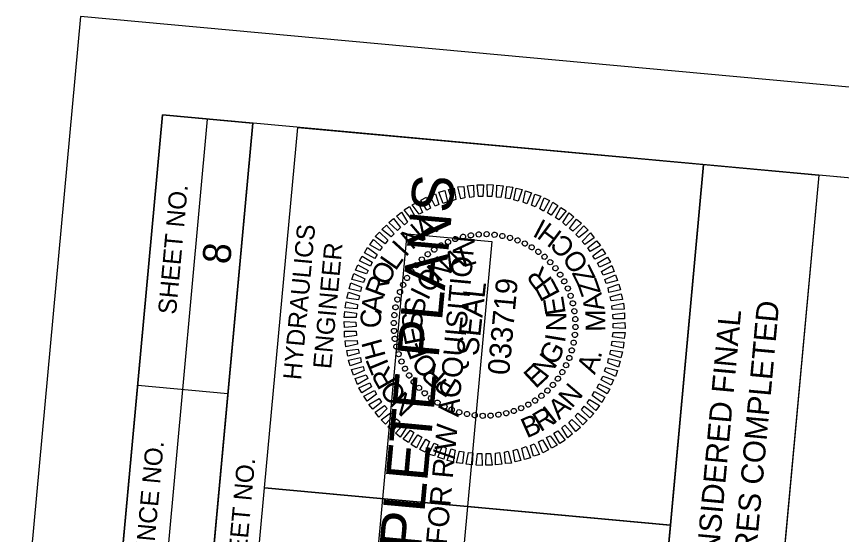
# Model space of a CAD drawing. Extents: x 2012234 to 2013485, y 445879 to 447846.
# Drawn here: x 2012372.3 to 2012600.1, y 447702.9 to 447846 of the extents above; entities that cross this region are included whole.
import ezdxf

# ---------------------------------------------------------------- set-up
doc = ezdxf.new("R2010")
doc.units = 0
for name, color, linetype in [('Sheet Clip Boundary CELL', 7, 'Continuous'), ('Sheet Data Field CELL', 7, 'Continuous'), ('Sheet Plan And Profile CELL', 7, 'Continuous'), ('Sheet Plot Border Outside CELL', 7, 'Continuous'), ('Sheet Professional Seal CELL', 7, 'Continuous'), ('Sheet Profile Grid Minor CELL', 7, 'Continuous'), ('Sheet Sticker Exception Certification CELL', 7, 'Continuous'), ('Sheet Sticker Incomplete CELL', 7, 'Continuous')]:
    doc.layers.add(name, color=color, linetype=linetype)

msp = doc.modelspace()

# ---------------------------------------------------------------- linework, layer by layer
at = {"layer": 'Sheet Clip Boundary CELL'}
msp.add_lwpolyline([(2012286.31, 446445.78), (2012511.43, 446429.21), (2012750.66, 446410.08), (2013333.05, 446362.08), (2013458.14, 447722.64), (2012593.82, 447802.11), (2012575.5, 447602.9), (2012460.65, 447613.46), (2012442.34, 447414.28), (2012375.93, 447420.39)], close=True, dxfattribs=at)
at = {"layer": 'Sheet Plan And Profile CELL'}
for p, q in [((2012406.74, 447618.42), (2012425.05, 447817.63)), ((2012419.18, 447617.27), (2012437.5, 447816.48)), ((2012405.74, 447744.09), (2012430.63, 447741.8)), ((2012440.79, 447715.76), (2012552.77, 447705.46))]:
    msp.add_line(p, q, dxfattribs=at)
for points in [[(2012412.56, 447818.78), (2012275.22, 446325.08), (2013320.81, 446228.94), (2013458.14, 447722.64)], [(2012394.24, 447619.57), (2012412.56, 447818.78), (2012437.5, 447816.48), (2012419.18, 447617.27)], [(2012440.79, 447715.76), (2012449.95, 447815.34), (2012561.97, 447805.04), (2012552.82, 447705.46)], [(2012431.63, 447616.13), (2012440.79, 447715.76), (2012552.82, 447705.46), (2012543.66, 447605.83)]]:
    msp.add_lwpolyline(points, close=True, dxfattribs=at)
at = {"layer": 'Sheet Plot Border Outside CELL'}
msp.add_lwpolyline([(2013329.68, 446052.39), (2013485.33, 447745.24), (2012389.95, 447845.96), (2012234.3, 446153.1)], close=True, dxfattribs=at)
at = {"layer": 'Sheet Professional Seal CELL'}
for p, q in [((2012497.69, 447785.54), (2012497.69, 447785.54)), ((2012499.92, 447785.74), (2012499.92, 447785.74)), ((2012502.08, 447785.84), (2012502.08, 447785.84)), ((2012504.28, 447785.69), (2012504.28, 447785.69)), ((2012506.46, 447785.34), (2012506.46, 447785.34)), ((2012491.44, 447783.71), (2012491.44, 447783.71)), ((2012493.48, 447784.52), (2012493.48, 447784.52)), ((2012495.54, 447785.14), (2012495.54, 447785.14)), ((2012508.56, 447784.79), (2012508.56, 447784.79)), ((2012510.61, 447784.15), (2012510.61, 447784.15)), ((2012512.64, 447783.26), (2012512.64, 447783.26)), ((2012487.59, 447781.65), (2012487.59, 447781.65)), ((2012489.45, 447782.73), (2012489.45, 447782.73)), ((2012514.55, 447782.18), (2012514.55, 447782.18)), ((2012516.4, 447781.01), (2012516.4, 447781.01)), ((2012484.17, 447778.9), (2012484.17, 447778.9)), ((2012485.81, 447780.31), (2012485.81, 447780.31)), ((2012518.08, 447779.6), (2012518.08, 447779.6)), ((2012482.67, 447777.28), (2012482.67, 447777.28)), ((2012519.7, 447778.1), (2012519.7, 447778.1)), ((2012521.1, 447776.46), (2012521.1, 447776.46)), ((2012481.26, 447775.6), (2012481.26, 447775.6)), ((2012522.45, 447774.68), (2012522.45, 447774.68)), ((2012479.01, 447771.85), (2012479.01, 447771.85)), ((2012480.08, 447773.75), (2012480.08, 447773.75)), ((2012523.53, 447772.82), (2012523.53, 447772.82)), ((2012478.12, 447769.82), (2012478.12, 447769.82)), ((2012524.5, 447770.83), (2012524.5, 447770.83)), ((2012477.48, 447767.77), (2012477.48, 447767.77)), ((2012525.32, 447768.79), (2012525.32, 447768.79)), ((2012476.93, 447765.66), (2012476.93, 447765.66)), ((2012525.93, 447766.73), (2012525.93, 447766.73)), ((2012476.58, 447763.48), (2012476.58, 447763.48)), ((2012526.34, 447764.58), (2012526.34, 447764.58)), ((2012476.43, 447761.29), (2012476.43, 447761.29)), ((2012501.53, 447760.74), (2012501.53, 447760.74)), ((2012526.54, 447762.35), (2012526.54, 447762.35)), ((2012476.53, 447759.12), (2012476.53, 447759.12)), ((2012526.64, 447760.19), (2012526.64, 447760.19)), ((2012476.73, 447756.89), (2012476.73, 447756.89)), ((2012526.14, 447755.81), (2012526.14, 447755.81)), ((2012526.49, 447757.99), (2012526.49, 447757.99)), ((2012477.13, 447754.74), (2012477.13, 447754.74)), ((2012525.59, 447753.7), (2012525.59, 447753.7)), ((2012477.75, 447752.68), (2012477.75, 447752.68)), ((2012524.95, 447751.65), (2012524.95, 447751.65)), ((2012478.56, 447750.65), (2012478.56, 447750.65)), ((2012524.06, 447749.63), (2012524.06, 447749.63)), ((2012479.53, 447748.65), (2012479.53, 447748.65)), ((2012480.62, 447746.79), (2012480.62, 447746.79)), ((2012522.98, 447747.72), (2012522.98, 447747.72)), ((2012481.96, 447745.01), (2012481.96, 447745.01)), ((2012521.81, 447745.87), (2012521.81, 447745.87)), ((2012483.37, 447743.38), (2012483.37, 447743.38)), ((2012518.89, 447742.57), (2012518.89, 447742.57)), ((2012520.4, 447744.19), (2012520.4, 447744.19)), ((2012484.99, 447741.87), (2012484.99, 447741.87)), ((2012486.66, 447740.46), (2012486.66, 447740.46)), ((2012515.48, 447739.82), (2012515.48, 447739.82)), ((2012517.26, 447741.16), (2012517.26, 447741.16)), ((2012488.51, 447739.29), (2012488.51, 447739.29)), ((2012490.42, 447738.21), (2012490.42, 447738.21)), ((2012511.62, 447737.77), (2012511.62, 447737.77)), ((2012513.62, 447738.74), (2012513.62, 447738.74)), ((2012492.45, 447737.32), (2012492.45, 447737.32)), ((2012494.5, 447736.68), (2012494.5, 447736.68)), ((2012496.61, 447736.13), (2012496.61, 447736.13)), ((2012498.79, 447735.78), (2012498.79, 447735.78)), ((2012500.98, 447735.63), (2012500.98, 447735.63)), ((2012503.15, 447735.73), (2012503.15, 447735.73)), ((2012505.38, 447735.93), (2012505.38, 447735.93)), ((2012507.52, 447736.33), (2012507.52, 447736.33)), ((2012509.59, 447736.95), (2012509.59, 447736.95))]:
    msp.add_line(p, q, dxfattribs=at)
for points in [[(2012495, 447795.58), (2012494.14, 447798.87), (2012495.81, 447799.02), (2012496.07, 447795.83)], [(2012497.44, 447795.96), (2012496.78, 447799.18), (2012498.5, 447799.33), (2012498.51, 447796.16)], [(2012499.87, 447796.19), (2012499.47, 447799.49), (2012501.18, 447799.48), (2012501.08, 447796.28)], [(2012502.29, 447796.27), (2012502.19, 447799.54), (2012503.89, 447799.48), (2012503.49, 447796.26)], [(2012504.78, 447796.09), (2012504.93, 447799.34), (2012506.62, 447799.18), (2012505.98, 447795.98)], [(2012507.27, 447795.81), (2012507.67, 447799.04), (2012509.3, 447798.78), (2012508.45, 447795.6)], [(2012487.88, 447793.52), (2012486.39, 447796.47), (2012487.99, 447796.98), (2012488.88, 447794.03)], [(2012490.11, 447794.32), (2012488.89, 447797.4), (2012490.54, 447797.9), (2012491.25, 447794.72)], [(2012492.53, 447795), (2012491.52, 447798.16), (2012493.11, 447798.57), (2012493.62, 447795.41)], [(2012509.63, 447795.34), (2012510.23, 447798.5), (2012511.9, 447798.14), (2012510.81, 447794.98)], [(2012512.14, 447794.71), (2012512.82, 447797.76), (2012514.48, 447797.25), (2012513.15, 447794.21)], [(2012514.47, 447793.84), (2012515.4, 447796.87), (2012517.01, 447796.37), (2012515.48, 447793.35)], [(2012483.41, 447791.32), (2012481.54, 447793.96), (2012483.07, 447794.77), (2012484.41, 447791.83)], [(2012485.57, 447792.43), (2012483.92, 447795.24), (2012485.5, 447796.05), (2012486.63, 447793.04)], [(2012516.79, 447792.87), (2012517.97, 447795.88), (2012519.45, 447795.09), (2012517.78, 447792.23)], [(2012518.89, 447791.68), (2012520.32, 447794.66), (2012521.79, 447793.77), (2012519.94, 447791.08)], [(2012481.33, 447790.01), (2012479.3, 447792.51), (2012480.74, 447793.43), (2012482.39, 447790.61)], [(2012521.09, 447790.47), (2012522.59, 447793.19), (2012524.07, 447792.31), (2012521.98, 447789.79)], [(2012477.47, 447786.8), (2012475.07, 447789.08), (2012476.37, 447790.16), (2012478.3, 447787.68)], [(2012479.38, 447788.43), (2012477.23, 447790.79), (2012478.54, 447791.87), (2012480.24, 447789.1)], [(2012523.12, 447789.08), (2012524.87, 447791.73), (2012526.17, 447790.61), (2012523.94, 447788.2)], [(2012524.97, 447787.4), (2012526.91, 447789.93), (2012528.27, 447788.86), (2012525.86, 447786.67)], [(2012475.75, 447785.05), (2012473.18, 447787.14), (2012474.4, 447788.34), (2012476.53, 447785.93)], [(2012526.73, 447785.73), (2012528.91, 447788.14), (2012530.1, 447786.93), (2012527.56, 447784.95)], [(2012474.07, 447783.14), (2012471.34, 447785.15), (2012472.51, 447786.35), (2012474.77, 447784.19)], [(2012528.46, 447783.82), (2012530.73, 447786.17), (2012531.76, 447784.82), (2012529.18, 447782.95)], [(2012472.55, 447781.33), (2012469.83, 447782.93), (2012470.82, 447784.35), (2012473.23, 447782.22)], [(2012530.05, 447782.01), (2012532.44, 447784), (2012533.53, 447782.7), (2012530.66, 447781)], [(2012471.19, 447779.14), (2012468.37, 447780.66), (2012469.21, 447782.14), (2012471.84, 447780.19)], [(2012531.41, 447779.88), (2012534, 447781.8), (2012534.92, 447780.36), (2012531.97, 447778.88)], [(2012470.04, 447776.99), (2012467.01, 447778.42), (2012467.73, 447779.76), (2012470.49, 447778.1)], [(2012532.73, 447777.85), (2012535.44, 447779.46), (2012536.27, 447778.08), (2012533.23, 447776.7)], [(2012468.94, 447774.83), (2012465.92, 447775.86), (2012466.56, 447777.36), (2012469.38, 447775.84)], [(2012533.77, 447775.55), (2012536.63, 447777.14), (2012537.29, 447775.52), (2012534.28, 447774.55)], [(2012468.07, 447772.5), (2012464.88, 447773.29), (2012465.43, 447774.95), (2012468.41, 447773.52)], [(2012534.77, 447773.3), (2012537.71, 447774.63), (2012538.26, 447773.02), (2012535.12, 447772.16)], [(2012467.29, 447770.01), (2012464.14, 447770.75), (2012464.54, 447772.37), (2012467.55, 447771.19)], [(2012535.62, 447771.01), (2012538.62, 447772.04), (2012539.08, 447770.49), (2012535.8, 447769.74)], [(2012466.67, 447767.66), (2012463.45, 447768.15), (2012463.9, 447769.77), (2012466.98, 447768.83)], [(2012466.29, 447765.18), (2012463.06, 447765.48), (2012463.26, 447767.12), (2012466.45, 447766.37)], [(2012536.19, 447768.5), (2012539.28, 447769.37), (2012539.59, 447767.78), (2012536.44, 447767.42)], [(2012536.62, 447766.05), (2012539.85, 447766.8), (2012540.04, 447765.08), (2012536.77, 447764.98)], [(2012466.02, 447762.8), (2012462.76, 447762.84), (2012462.96, 447764.48), (2012466.18, 447763.99)], [(2012536.94, 447763.61), (2012540.2, 447764.11), (2012540.2, 447762.45), (2012536.98, 447762.4)], [(2012466.04, 447760.28), (2012462.81, 447760.03), (2012462.76, 447761.74), (2012466, 447761.49)], [(2012537.02, 447761.19), (2012540.26, 447761.44), (2012540.3, 447759.73), (2012537.06, 447759.98)], [(2012466.12, 447757.87), (2012462.86, 447757.36), (2012462.86, 447759.02), (2012466.08, 447759.07)], [(2012537.04, 447758.68), (2012540.3, 447758.63), (2012540.1, 447756.99), (2012536.88, 447757.49)], [(2012466.45, 447755.43), (2012463.22, 447754.67), (2012463.02, 447756.39), (2012466.3, 447756.49)], [(2012536.77, 447756.29), (2012540.01, 447755.99), (2012539.81, 447754.35), (2012536.61, 447755.1)], [(2012466.88, 447752.98), (2012463.78, 447752.11), (2012463.48, 447753.69), (2012466.62, 447754.05)], [(2012536.4, 447753.81), (2012539.61, 447753.32), (2012539.16, 447751.7), (2012536.09, 447752.64)], [(2012467.45, 447750.46), (2012464.44, 447749.43), (2012463.98, 447750.98), (2012467.26, 447751.74)], [(2012535.78, 447751.46), (2012538.92, 447750.72), (2012538.52, 447749.1), (2012535.52, 447750.28)], [(2012468.29, 447748.18), (2012465.36, 447746.84), (2012464.8, 447748.45), (2012467.95, 447749.31)], [(2012535, 447748.97), (2012538.19, 447748.18), (2012537.63, 447746.52), (2012534.65, 447747.95)], [(2012469.29, 447745.93), (2012466.43, 447744.33), (2012465.78, 447745.95), (2012468.78, 447746.93)], [(2012534.13, 447746.64), (2012537.15, 447745.61), (2012536.51, 447744.11), (2012533.68, 447745.63)], [(2012470.33, 447743.62), (2012467.63, 447742.01), (2012466.8, 447743.39), (2012469.84, 447744.77)], [(2012533.03, 447744.48), (2012536.06, 447743.05), (2012535.33, 447741.71), (2012532.57, 447743.37)], [(2012471.65, 447741.59), (2012469.07, 447739.67), (2012468.15, 447741.11), (2012471.09, 447742.6)], [(2012531.87, 447742.33), (2012534.7, 447740.82), (2012533.86, 447739.34), (2012531.23, 447741.29)], [(2012473.01, 447739.46), (2012470.62, 447737.47), (2012469.54, 447738.77), (2012472.4, 447740.47)], [(2012530.52, 447740.15), (2012533.23, 447738.54), (2012532.25, 447737.12), (2012529.83, 447739.25)], [(2012474.61, 447737.65), (2012472.33, 447735.3), (2012471.3, 447736.65), (2012473.88, 447738.52)], [(2012529, 447738.33), (2012531.72, 447736.32), (2012530.56, 447735.12), (2012528.3, 447737.29)], [(2012476.34, 447735.74), (2012474.16, 447733.33), (2012472.96, 447734.54), (2012475.51, 447736.52)], [(2012527.31, 447736.42), (2012529.88, 447734.33), (2012528.67, 447733.14), (2012526.53, 447735.54)], [(2012478.09, 447734.07), (2012476.15, 447731.54), (2012474.8, 447732.62), (2012477.21, 447734.8)], [(2012479.95, 447732.39), (2012478.2, 447729.74), (2012476.89, 447730.87), (2012479.12, 447733.27)], [(2012523.69, 447733.04), (2012525.83, 447730.68), (2012524.53, 447729.6), (2012522.82, 447732.37)], [(2012525.6, 447734.67), (2012528, 447732.39), (2012526.69, 447731.31), (2012524.76, 447733.8)], [(2012481.98, 447731), (2012480.47, 447728.28), (2012479, 447729.17), (2012481.09, 447731.69)], [(2012521.74, 447731.46), (2012523.77, 447728.97), (2012522.33, 447728.04), (2012520.68, 447730.86)], [(2012484.18, 447729.8), (2012482.75, 447726.81), (2012481.27, 447727.7), (2012483.13, 447730.39)], [(2012486.28, 447728.6), (2012485.1, 447725.59), (2012483.61, 447726.38), (2012485.28, 447729.24)], [(2012517.5, 447729.04), (2012519.15, 447726.23), (2012517.57, 447725.42), (2012516.44, 447728.44)], [(2012519.66, 447730.15), (2012521.52, 447727.52), (2012519.99, 447726.7), (2012518.66, 447729.64)], [(2012488.6, 447727.63), (2012487.67, 447724.6), (2012486.06, 447725.1), (2012487.59, 447728.13)], [(2012490.93, 447726.76), (2012490.25, 447723.71), (2012488.58, 447724.22), (2012489.92, 447727.26)], [(2012493.43, 447726.13), (2012492.84, 447722.97), (2012491.16, 447723.33), (2012492.26, 447726.49)], [(2012510.53, 447726.47), (2012511.55, 447723.31), (2012509.95, 447722.91), (2012509.44, 447726.07)], [(2012512.96, 447727.15), (2012514.18, 447724.07), (2012512.53, 447723.57), (2012511.81, 447726.75)], [(2012515.19, 447727.95), (2012516.67, 447725), (2012515.07, 447724.49), (2012514.19, 447727.44)], [(2012495.8, 447725.66), (2012495.4, 447722.44), (2012493.77, 447722.69), (2012494.61, 447725.87)], [(2012498.28, 447725.39), (2012498.13, 447722.13), (2012496.44, 447722.29), (2012497.09, 447725.49)], [(2012500.78, 447725.21), (2012500.88, 447721.93), (2012499.18, 447721.99), (2012499.57, 447725.22)], [(2012503.19, 447725.28), (2012503.59, 447721.98), (2012501.89, 447721.99), (2012501.98, 447725.2)], [(2012505.62, 447725.51), (2012506.28, 447722.29), (2012504.56, 447722.15), (2012504.55, 447725.31)], [(2012508.07, 447725.89), (2012508.92, 447722.6), (2012507.25, 447722.45), (2012506.99, 447725.64)]]:
    msp.add_lwpolyline(points, close=True, dxfattribs=at)
for centre, major_axis in [((2012495.57, 447785.1), (-0.171, 0.699)), ((2012497.72, 447785.52), (-0.109, 0.712)), ((2012499.89, 447785.76), (-0.047, 0.718)), ((2012502.08, 447785.81), (0.016, 0.72)), ((2012504.26, 447785.67), (0.078, 0.716)), ((2012506.43, 447785.33), (0.141, 0.706)), ((2012508.55, 447784.81), (0.202, 0.691)), ((2012489.47, 447782.72), (-0.346, 0.631)), ((2012491.43, 447783.69), (-0.29, 0.659)), ((2012493.47, 447784.49), (-0.231, 0.682)), ((2012510.62, 447784.11), (0.261, 0.671)), ((2012512.63, 447783.23), (0.318, 0.646)), ((2012485.84, 447780.3), (-0.451, 0.562)), ((2012487.6, 447781.59), (-0.4, 0.599)), ((2012514.54, 447782.18), (0.374, 0.616)), ((2012516.36, 447780.96), (0.426, 0.581)), ((2012484.19, 447778.85), (-0.498, 0.52)), ((2012518.07, 447779.59), (0.475, 0.541)), ((2012519.65, 447778.08), (0.52, 0.498)), ((2012481.31, 447775.57), (-0.581, 0.426)), ((2012482.68, 447777.27), (-0.541, 0.475)), ((2012521.09, 447776.43), (0.562, 0.451)), ((2012480.09, 447773.75), (-0.616, 0.374)), ((2012522.39, 447774.67), (0.599, 0.4)), ((2012479.04, 447771.83), (-0.646, 0.318)), ((2012523.52, 447772.8), (0.631, 0.346)), ((2012478.16, 447769.83), (-0.671, 0.261)), ((2012524.49, 447770.84), (0.659, 0.29)), ((2012525.28, 447768.8), (0.682, 0.231)), ((2012477.45, 447767.76), (-0.691, 0.202)), ((2012525.89, 447766.7), (0.699, 0.171)), ((2012476.93, 447765.63), (-0.706, 0.141)), ((2012526.32, 447764.55), (0.712, 0.109)), ((2012476.6, 447763.47), (-0.716, 0.078)), ((2012526.56, 447762.37), (0.718, 0.047)), ((2012476.46, 447761.28), (-0.72, 0.016)), ((2012526.61, 447760.19), (0.72, -0.016)), ((2012476.51, 447759.1), (-0.718, -0.047)), ((2012526.46, 447758), (0.716, -0.078)), ((2012476.74, 447756.92), (-0.712, -0.109)), ((2012526.13, 447755.84), (0.706, -0.141)), ((2012477.17, 447754.78), (-0.699, -0.171)), ((2012477.78, 447752.68), (-0.682, -0.231)), ((2012525.61, 447753.72), (0.691, -0.202)), ((2012478.58, 447750.64), (-0.659, -0.29)), ((2012524.91, 447751.64), (0.671, -0.261)), ((2012479.54, 447748.67), (-0.631, -0.346)), ((2012524.03, 447749.64), (0.646, -0.318)), ((2012480.68, 447746.8), (-0.599, -0.4)), ((2012521.76, 447745.9), (0.581, -0.426)), ((2012522.97, 447747.72), (0.616, -0.374)), ((2012481.97, 447745.04), (-0.562, -0.451)), ((2012520.39, 447744.2), (0.541, -0.475)), ((2012483.41, 447743.39), (-0.52, -0.498)), ((2012485, 447741.88), (-0.475, -0.541)), ((2012518.87, 447742.62), (0.498, -0.52)), ((2012486.7, 447740.51), (-0.426, -0.581)), ((2012488.52, 447739.3), (-0.374, -0.616)), ((2012515.47, 447739.88), (0.4, -0.599)), ((2012517.23, 447741.18), (0.451, -0.562)), ((2012490.44, 447738.24), (-0.318, -0.646)), ((2012492.44, 447737.36), (-0.261, -0.671)), ((2012509.59, 447736.99), (0.231, -0.682)), ((2012511.63, 447737.78), (0.29, -0.659)), ((2012513.59, 447738.75), (0.346, -0.631)), ((2012494.51, 447736.66), (-0.202, -0.691)), ((2012496.64, 447736.14), (-0.141, -0.706)), ((2012498.8, 447735.81), (-0.078, -0.716)), ((2012500.98, 447735.66), (-0.016, -0.72)), ((2012503.17, 447735.71), (0.047, -0.718)), ((2012505.35, 447735.95), (0.109, -0.712)), ((2012507.49, 447736.37), (0.171, -0.699))]:
    msp.add_ellipse(centre, major_axis=major_axis, ratio=0.999708, dxfattribs=at)
at = {"layer": 'Sheet Sticker Exception Certification CELL'}
for p, q in [((2012543.64, 447605.83), (2012561.96, 447805.04)), ((2012561.97, 447805.04), (2012593.82, 447802.11)), ((2012593.8, 447802.11), (2012575.49, 447602.9))]:
    msp.add_line(p, q, dxfattribs=at)
at = {"layer": 'Sheet Sticker Incomplete CELL'}
msp.add_lwpolyline([(2012490.08, 447637.42), (2012466.67, 447639.57), (2012480.13, 447785.95), (2012503.53, 447783.8)], close=True, dxfattribs=at)

# ---------------------------------------------------------------- texts
at = {"layer": 'Sheet Data Field CELL'}
msp.add_text('8', height=7.75, rotation=84.7467, dxfattribs=at).set_placement((2012431.24, 447777.35))
at = {"layer": 'Sheet Plan And Profile CELL'}
for s, height, p in [('SHEET NO.', 5, (2012416.31, 447763.5)), ('HYDRAULICS', 5, (2012450.85, 447745.41)), ('ENGINEER', 5, (2012459.11, 447748.47)), ('PROJECT REFERENCE NO.', 5.0001, (2012404.93, 447640.88)), ('R/W SHEET NO.', 5.0001, (2012433.56, 447673.19))]:
    msp.add_text(s, height=height, rotation=84.7467, dxfattribs=at).set_placement(p)
at = {"layer": 'Sheet Professional Seal CELL'}
for s, height, rotation, p in [('A', 5.64, 33.3638, (2012484.64, 447783.98)), ('N', 5.64, 40.5656, (2012481.43, 447781.31)), ('I', 5.64, 47.7668, (2012479.69, 447779.31)), ('A', 5.64, 26.5069, (2012491.9, 447774.98)), ('L', 5.64, 17.1475, (2012495.51, 447776.6)), ('L', 5.64, 54.9675, (2012476.93, 447775.5)), ('N', 5.64, 45.2233, (2012489.05, 447772.38)), ('O', 5.64, 62.1678, (2012474.69, 447771.29)), ('R', 5.64, 127.2281, (2012520.5, 447773.15)), ('R', 5.64, 69.3678, (2012473.63, 447768.02)), ('O', 5.64, 54.5801, (2012486.75, 447769.23)), ('SEAL', 5.998, 83.7467, (2012499.73, 447752.01)), ('E', 5.64, 117.8707, (2012522.51, 447769.4)), ('I', 5.64, 63.9363, (2012485.87, 447767.3)), ('A', 5.64, 83.767, (2012473.05, 447763.86)), ('S', 5.64, 82.6471, (2012484.78, 447763.08)), ('E', 5.64, 99.1584, (2012523.97, 447763.94)), ('C', 5.64, 90.9665, (2012472.99, 447759.9)), ('S', 5.64, 92.0023, (2012484.5, 447759.49)), ('N', 5.64, 89.803, (2012524.11, 447758.96)), ('E', 5.64, 101.3577, (2012485.23, 447755.96)), ('H', 5.64, 105.3661, (2012474.28, 447752.14)), ('F', 5.64, 110.7137, (2012486.43, 447752.63)), ('G', 5.64, 61.7369, (2012521.17, 447749.29)), ('I', 5.64, 80.4479, (2012523.66, 447755.64)), ('T', 5.64, 112.5664, (2012475.63, 447748.76)), ('O', 5.64, 129.4279, (2012489.06, 447749.08)), ('N', 5.64, 52.3806, (2012518.58, 447745.71)), ('R', 5.64, 119.7672, (2012477.51, 447745.17)), ('R', 5.64, 138.7863, (2012491.34, 447747.11)), ('E', 5.64, 43.0235, (2012515.62, 447742.97)), ('O', 5.64, 126.9684, (2012480.28, 447741.45)), ('P', 5.64, 148.1455, (2012494.38, 447745.23)), ('N', 5.64, 134.1702, (2012482.95, 447738.9))]:
    msp.add_text(s, height=height, rotation=rotation, dxfattribs=at).set_placement(p)
at = {"layer": 'Sheet Profile Grid Minor CELL'}
for s, height, rotation, p in [('I', 5.5, 152.3393, (2012518.86, 447789.32)), ('H', 5.5, 143.0945, (2012523.23, 447786.17)), ('C', 5.5, 134.2218, (2012526.89, 447782.52)), ('O', 5.5, 123.5173, (2012530.49, 447777.43)), ('Z', 5.5, 116.3905, (2012532.34, 447773.71)), ('033719', 5.998, 84.7467, (2012508.29, 447746.74)), ('Z', 5.5, 109.2637, (2012533.71, 447769.78)), ('A', 5.5, 101.0779, (2012534.67, 447765.11)), ('M', 5.5, 90.402, (2012534.91, 447758.9)), ('A', 5.5, 69.0359, (2012531.95, 447746.86)), ('.', 5.5, 77.2217, (2012533.61, 447751.33)), ('N', 5.5, 49.6591, (2012525.62, 447737.56)), ('A', 5.5, 41.4733, (2012522.07, 447734.36)), ('R', 5.5, 31.0264, (2012516.95, 447731.08)), ('I', 5.5, 37.9528, (2012520.42, 447733.15)), ('B', 5.5, 23.8996, (2012513.15, 447729.39))]:
    msp.add_text(s, height=height, rotation=rotation, dxfattribs=at).set_placement(p)
at = {"layer": 'Sheet Sticker Exception Certification CELL'}
for s, p in [('UNLESS ALL SIGNATURES COMPLETED', (2012568.42, 447609.47)), ('DOCUMENT NOT CONSIDERED FINAL', (2012558.73, 447616.12))]:
    msp.add_text(s, height=6.124, rotation=84.7467, dxfattribs=at).set_placement(p)
at = {"layer": 'Sheet Sticker Incomplete CELL'}
for s, height, p in [('INCOMPLETE PLANS', 11.52, (2012479.24, 447647.4)), ('DO NOT USE FOR R/W ACQUISITION', 5.76, (2012486.46, 447650))]:
    msp.add_text(s, height=height, rotation=84.7467, dxfattribs=at).set_placement(p)

doc.saveas('drawing.dxf')
